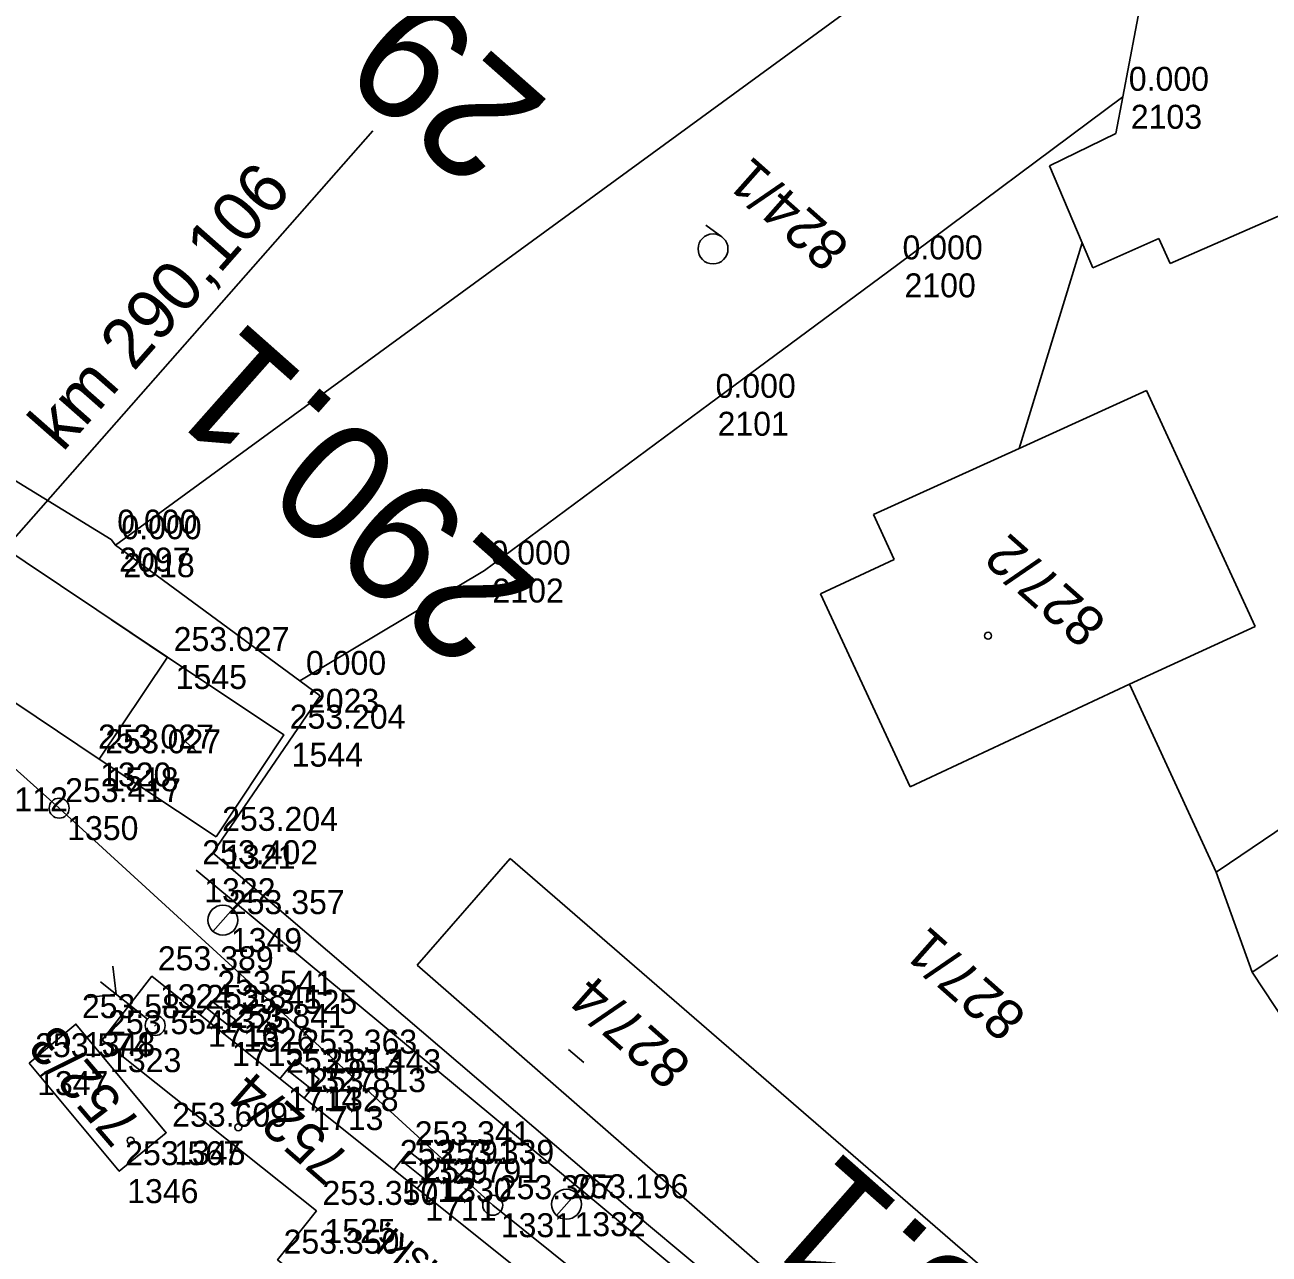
# Model space of a CAD drawing. Extents: x -496688 to -495455, y -1089309 to -1088026.
# Drawn here: x -496316.3 to -496254, y -1088279.1 to -1088217.5 of the extents above; entities that cross this region are included whole.
import ezdxf

# ---------------------------------------------------------------- set-up
doc = ezdxf.new("R2010")
doc.units = 0
for name, color, linetype in [('Vrstva 10', 7, 'Continuous'), ('Vrstva 17', 7, 'Continuous'), ('Vrstva 20', 7, 'Continuous'), ('Vrstva 23', 7, 'Continuous'), ('Vrstva 29', 7, 'Continuous'), ('Vrstva 36', 7, 'Continuous'), ('Vrstva 47', 7, 'Continuous'), ('Vrstva 50', 7, 'Continuous'), ('Vrstva 53', 7, 'Continuous'), ('Vrstva 55', 7, 'Continuous'), ('Vrstva 57', 7, 'Continuous'), ('Vrstva 58', 7, 'Continuous'), ('Vrstva 59', 7, 'Continuous'), ('Vrstva 60', 7, 'Continuous'), ('Vrstva 61', 7, 'Continuous'), ('Vrstva 7', 7, 'Continuous')]:
    doc.layers.add(name, color=color, linetype=linetype)

msp = doc.modelspace()

# ---------------------------------------------------------------- linework, layer by layer
at = {"layer": 'Vrstva 10'}
msp.add_line((-496340.44, -1088269.992), (-496298.917, -1088222.84), dxfattribs=at)
at = {"layer": 'Vrstva 17'}
msp.add_lwpolyline([(-496307.762, -1088259.861), (-496269.8, -1088291.38), (-496248.423, -1088308.125)], dxfattribs=at)
at = {"layer": 'Vrstva 20'}
msp.add_lwpolyline([(-496316.13, -1088269.522), (-496313.788, -1088267.568), (-496309.268, -1088273.004), (-496311.621, -1088274.929), (-496316.13, -1088269.522)], dxfattribs=at)
at = {"layer": 'Vrstva 23'}
for p, q in [((-496259.78, -1088212.78), (-496261.37, -1088221.14)), ((-496261.37, -1088221.14), (-496261.72, -1088222.97)), ((-496261.72, -1088222.97), (-496265.04, -1088224.59)), ((-496265.04, -1088224.59), (-496263.4, -1088228.45)), ((-496259, -1088229.48), (-496251.75, -1088226.32)), ((-496263.4, -1088228.45), (-496262.87, -1088229.7)), ((-496262.87, -1088229.7), (-496259.56, -1088228.24)), ((-496259.56, -1088228.24), (-496259, -1088229.48)), ((-496260.18, -1088235.84), (-496266.56, -1088238.74)), ((-496254.74, -1088247.66), (-496260.18, -1088235.84)), ((-496266.56, -1088238.74), (-496273.85, -1088242.06)), ((-496273.85, -1088242.06), (-496272.81, -1088244.31)), ((-496272.81, -1088244.31), (-496276.5, -1088246.03)), ((-496276.5, -1088246.03), (-496272.01, -1088255.68)), ((-496261.03, -1088250.54), (-496254.74, -1088247.66)), ((-496272.01, -1088255.68), (-496261.03, -1088250.54)), ((-496249.52, -1088261.41), (-496254.9, -1088264.97)), ((-496254.9, -1088264.97), (-496248.71, -1088274.32)), ((-496307.572, -1088267.101), (-496307.006, -1088266.394)), ((-496307.006, -1088266.394), (-496305.804, -1088267.347)), ((-496306.08, -1088267.692), (-496307.278, -1088266.733)), ((-496305.804, -1088267.347), (-496306.374, -1088268.059)), ((-496303.569, -1088270.304), (-496302.8, -1088269.342)), ((-496302.8, -1088269.342), (-496301.602, -1088270.326)), ((-496303.205, -1088269.848), (-496301.994, -1088270.816)), ((-496301.602, -1088270.326), (-496302.359, -1088271.272)), ((-496297.869, -1088274.865), (-496297.123, -1088273.932)), ((-496297.123, -1088273.932), (-496295.941, -1088274.86)), ((-496297.491, -1088274.392), (-496296.318, -1088275.331)), ((-496295.941, -1088274.86), (-496296.696, -1088275.803))]:
    msp.add_line(p, q, dxfattribs=at)
for points in [[(-496306.766, -1088258.19), (-496312.619, -1088254.307), (-496335.736, -1088238.781), (-496332.365, -1088233.683), (-496309.194, -1088249.189), (-496303.385, -1088253.076), (-496306.766, -1088258.19)], [(-496312.619, -1088254.307), (-496309.194, -1088249.189)], [(-496312.479, -1088268.372), (-496309.984, -1088265.171), (-496290.696, -1088280.604), (-496295.221, -1088286.171), (-496303.69, -1088279.36), (-496301.745, -1088276.917), (-496312.479, -1088268.372)]]:
    msp.add_lwpolyline(points, dxfattribs=at)
at = {"layer": 'Vrstva 29'}
msp.add_lwpolyline([(-496228.726, -1088272.089), (-496242.207, -1088304.985), (-496270.468, -1088294.64), (-496292.916, -1088276.634), (-496314.625, -1088256.754), (-496338.738, -1088235.152), (-496372.173, -1088205.903), (-496403.1, -1088180.315), (-496426.737, -1088162.268), (-496430.704, -1088173.66)], dxfattribs=at)
at = {"layer": 'Vrstva 36'}
for centre in [(-496314.625, -1088256.754), (-496292.916, -1088276.634)]:
    msp.add_circle(centre, 0.5, dxfattribs=at)
at = {"layer": 'Vrstva 47'}
for p, q in [((-496306.928, -1088262.922), (-496305.271, -1088261.05)), ((-496289.722, -1088277.146), (-496288.065, -1088275.274))]:
    msp.add_line(p, q, dxfattribs=at)
for centre in [(-496306.431, -1088262.36), (-496289.225, -1088276.584)]:
    msp.add_circle(centre, 0.75, dxfattribs=at)
at = {"layer": 'Vrstva 50'}
for p, q in [((-496311.77, -1088266.074), (-496311.931, -1088264.657)), ((-496310.208, -1088267.324), (-496312.549, -1088265.449)), ((-496311.77, -1088266.074), (-496313.175, -1088266.229)), ((-496309.849, -1088267.676), (-496309.787, -1088267.598))]:
    msp.add_line(p, q, dxfattribs=at)
msp.add_circle((-496309.818, -1088267.637), 0.5, dxfattribs=at)
at = {"layer": 'Vrstva 53'}
for points in [[(-496539.03, -1088065.6), (-496535.97, -1088067.83), (-496531.62, -1088071.46), (-496507.63, -1088096.03), (-496458.59, -1088146.6), (-496452.94, -1088142.96), (-496452.25, -1088138.8), (-496443.22, -1088147.27), (-496395.64, -1088185.72), (-496395.1, -1088185.29), (-496369.57, -1088204.88), (-496360, -1088212.22), (-496349.3, -1088220.43), (-496330.37, -1088232.05), (-496312.02, -1088243.31), (-496311.81, -1088243.59), (-496302.57, -1088250.38)], [(-496302.57, -1088250.38), (-496293.33, -1088244.86), (-496282.06, -1088236.51), (-496272.7, -1088229.58), (-496261.37, -1088221.14), (-496259.78, -1088212.78), (-496258.79, -1088209.96), (-496249.04, -1088205.74), (-496247.06, -1088204.88), (-496237.12, -1088227.8), (-496230.93, -1088242.07), (-496224.34, -1088239.32), (-496222.24, -1088238.44), (-496221.74, -1088238.24), (-496217.87, -1088236.62), (-496206.35, -1088231.82), (-496205.03, -1088234.9), (-496199.66, -1088247.57), (-496188.02, -1088275.91)]]:
    msp.add_lwpolyline(points, dxfattribs=at)
at = {"layer": 'Vrstva 55'}
for p, q in [((-496254.42, -1088201.7), (-496311.81, -1088243.59)), ((-496263.4, -1088228.45), (-496266.56, -1088238.74)), ((-496311.81, -1088243.59), (-496312.02, -1088243.31)), ((-496312.01, -1088247.33), (-496309.2, -1088249.21)), ((-496241.58, -1088249.7), (-496256.02, -1088259.51)), ((-496302.57, -1088250.38), (-496301.558, -1088251.123)), ((-496301.558, -1088251.123), (-496306.928, -1088258.99)), ((-496261.03, -1088250.54), (-496256.69, -1088259.96)), ((-496306.928, -1088258.99), (-496285.12, -1088277.63)), ((-496296.7, -1088264.61), (-496292.05, -1088259.28)), ((-496292.05, -1088259.28), (-496264.72, -1088282.93)), ((-496256.02, -1088259.51), (-496256.69, -1088259.96)), ((-496256.69, -1088259.96), (-496254.9, -1088264.97)), ((-496269.47, -1088288.37), (-496296.7, -1088264.61)), ((-496285.12, -1088277.63), (-496271.2, -1088289.24))]:
    msp.add_line(p, q, dxfattribs=at)
at = {"layer": 'Vrstva 58'}
msp.add_line((-496281.445, -1088228.152), (-496282.251, -1088227.561), dxfattribs=at)
msp.add_circle((-496281.888, -1088228.757), 0.75, dxfattribs=at)
at = {"layer": 'Vrstva 59'}
for p, q in [((-496307.662, -1088253.987), (-496308.41, -1088253.323)), ((-496288.364, -1088269.495), (-496289.118, -1088268.837))]:
    msp.add_line(p, q, dxfattribs=at)
for centre in [(-496268.118, -1088248.123), (-496305.659, -1088272.733), (-496311.048, -1088273.4)]:
    msp.add_circle(centre, 0.175, dxfattribs=at)
at = {"layer": 'Vrstva 60'}
for p, q in [((-496261.37, -1088221.14), (-496261.37, -1088221.14)), ((-496261.37, -1088221.14), (-496261.37, -1088221.14)), ((-496272.7, -1088229.58), (-496272.7, -1088229.58)), ((-496272.7, -1088229.58), (-496272.7, -1088229.58)), ((-496282.06, -1088236.51), (-496282.06, -1088236.51)), ((-496282.06, -1088236.51), (-496282.06, -1088236.51)), ((-496312.02, -1088243.31), (-496312.02, -1088243.31)), ((-496312.02, -1088243.31), (-496312.02, -1088243.31)), ((-496311.81, -1088243.59), (-496311.81, -1088243.59)), ((-496311.81, -1088243.59), (-496311.81, -1088243.59)), ((-496293.33, -1088244.86), (-496293.33, -1088244.86)), ((-496293.33, -1088244.86), (-496293.33, -1088244.86)), ((-496309.194, -1088249.189), (-496309.194, -1088249.189)), ((-496309.194, -1088249.189), (-496309.194, -1088249.189)), ((-496302.57, -1088250.38), (-496302.57, -1088250.38)), ((-496302.57, -1088250.38), (-496302.57, -1088250.38)), ((-496303.385, -1088253.076), (-496303.385, -1088253.076)), ((-496303.385, -1088253.076), (-496303.385, -1088253.076)), ((-496312.977, -1088254.069), (-496312.977, -1088254.069)), ((-496312.977, -1088254.069), (-496312.977, -1088254.069)), ((-496312.619, -1088254.307), (-496312.619, -1088254.307)), ((-496312.619, -1088254.307), (-496312.619, -1088254.307)), ((-496314.625, -1088256.754), (-496314.625, -1088256.754)), ((-496314.625, -1088256.754), (-496314.625, -1088256.754)), ((-496306.766, -1088258.19), (-496306.766, -1088258.19)), ((-496306.766, -1088258.19), (-496306.766, -1088258.19)), ((-496307.762, -1088259.861), (-496307.762, -1088259.861)), ((-496307.762, -1088259.861), (-496307.762, -1088259.861)), ((-496306.431, -1088262.36), (-496306.431, -1088262.36)), ((-496306.431, -1088262.36), (-496306.431, -1088262.36)), ((-496309.984, -1088265.171), (-496309.984, -1088265.171)), ((-496309.984, -1088265.171), (-496309.984, -1088265.171)), ((-496307.006, -1088266.394), (-496307.006, -1088266.394)), ((-496307.006, -1088266.394), (-496307.006, -1088266.394)), ((-496307.572, -1088267.101), (-496307.572, -1088267.101)), ((-496307.572, -1088267.101), (-496307.572, -1088267.101)), ((-496313.788, -1088267.568), (-496313.788, -1088267.568)), ((-496313.788, -1088267.568), (-496313.788, -1088267.568)), ((-496305.804, -1088267.347), (-496305.804, -1088267.347)), ((-496305.804, -1088267.347), (-496305.804, -1088267.347)), ((-496312.479, -1088268.372), (-496312.479, -1088268.372)), ((-496312.479, -1088268.372), (-496312.479, -1088268.372)), ((-496306.374, -1088268.059), (-496306.374, -1088268.059)), ((-496306.374, -1088268.059), (-496306.374, -1088268.059)), ((-496316.13, -1088269.522), (-496316.13, -1088269.522)), ((-496316.13, -1088269.522), (-496316.13, -1088269.522)), ((-496302.8, -1088269.342), (-496302.8, -1088269.342)), ((-496302.8, -1088269.342), (-496302.8, -1088269.342)), ((-496303.569, -1088270.304), (-496303.569, -1088270.304)), ((-496303.569, -1088270.304), (-496303.569, -1088270.304)), ((-496301.602, -1088270.326), (-496301.602, -1088270.326)), ((-496301.602, -1088270.326), (-496301.602, -1088270.326)), ((-496302.359, -1088271.272), (-496302.359, -1088271.272)), ((-496302.359, -1088271.272), (-496302.359, -1088271.272)), ((-496309.268, -1088273.004), (-496309.268, -1088273.004)), ((-496309.268, -1088273.004), (-496309.268, -1088273.004)), ((-496297.123, -1088273.932), (-496297.123, -1088273.932)), ((-496297.123, -1088273.932), (-496297.123, -1088273.932)), ((-496311.621, -1088274.929), (-496311.621, -1088274.929)), ((-496311.621, -1088274.929), (-496311.621, -1088274.929)), ((-496297.869, -1088274.865), (-496297.869, -1088274.865)), ((-496297.869, -1088274.865), (-496297.869, -1088274.865)), ((-496295.941, -1088274.86), (-496295.941, -1088274.86)), ((-496295.941, -1088274.86), (-496295.941, -1088274.86)), ((-496296.696, -1088275.803), (-496296.696, -1088275.803)), ((-496296.696, -1088275.803), (-496296.696, -1088275.803)), ((-496292.916, -1088276.634), (-496292.916, -1088276.634)), ((-496292.916, -1088276.634), (-496292.916, -1088276.634)), ((-496289.225, -1088276.584), (-496289.225, -1088276.584)), ((-496289.225, -1088276.584), (-496289.225, -1088276.584)), ((-496301.745, -1088276.917), (-496301.745, -1088276.917)), ((-496301.745, -1088276.917), (-496301.745, -1088276.917))]:
    msp.add_line(p, q, dxfattribs=at)

# ---------------------------------------------------------------- texts
at = {"layer": 'Vrstva 10'}
msp.add_text('km 290,106', height=2.5, rotation=48.63225, dxfattribs=at).set_placement((-496314.458, -1088238.975))
at = {"layer": 'Vrstva 23'}
msp.add_text('Uh.skl.', height=1.5, rotation=141.19281, dxfattribs=at).set_placement((-496293.535, -1088281.172))
at = {"layer": 'Vrstva 57'}
for s, rotation, p in [('824/1', 138.47617, (-496274.947, -1088228.521)), ('827/2', 138.47617, (-496262.089, -1088247.351)), ('827/1', 138.47617, (-496266.095, -1088267.067)), ('827/4', 138.47617, (-496282.871, -1088269.463)), ('752/3', 130.50406, (-496310.417, -1088272.555)), ('752/4', 138.89312, (-496299.956, -1088274.216))]:
    msp.add_text(s, height=2, rotation=rotation, dxfattribs=at).set_placement(p)
at = {"layer": 'Vrstva 60'}
for s, p in [('2103', (-496260.97, -1088222.74)), ('2103', (-496260.97, -1088222.74)), ('2100', (-496272.3, -1088231.18)), ('2100', (-496272.3, -1088231.18)), ('2101', (-496281.66, -1088238.11)), ('2101', (-496281.66, -1088238.11)), ('2097', (-496311.62, -1088244.91)), ('2097', (-496311.62, -1088244.91)), ('2018', (-496311.41, -1088245.19)), ('2018', (-496311.41, -1088245.19)), ('2102', (-496292.93, -1088246.46)), ('2102', (-496292.93, -1088246.46)), ('1545', (-496308.794, -1088250.789)), ('1545', (-496308.794, -1088250.789)), ('2023', (-496302.17, -1088251.98)), ('2023', (-496302.17, -1088251.98)), ('1544', (-496302.985, -1088254.676)), ('1544', (-496302.985, -1088254.676)), ('1320', (-496312.577, -1088255.669)), ('1320', (-496312.577, -1088255.669)), ('1518', (-496312.219, -1088255.907)), ('1518', (-496312.219, -1088255.907)), ('1350', (-496314.225, -1088258.354)), ('1350', (-496314.225, -1088258.354)), ('1321', (-496306.366, -1088259.79)), ('1321', (-496306.366, -1088259.79)), ('1322', (-496307.362, -1088261.461)), ('1322', (-496307.362, -1088261.461)), ('1349', (-496306.031, -1088263.96)), ('1349', (-496306.031, -1088263.96)), ('1324', (-496309.584, -1088266.771)), ('1324', (-496309.584, -1088266.771)), ('1325', (-496306.606, -1088267.994)), ('1325', (-496306.606, -1088267.994)), ('1348', (-496313.388, -1088269.168)), ('1348', (-496313.388, -1088269.168)), ('1716', (-496307.172, -1088268.701)), ('1716', (-496307.172, -1088268.701)), ('1326', (-496305.404, -1088268.947)), ('1326', (-496305.404, -1088268.947)), ('1715', (-496305.974, -1088269.659)), ('1715', (-496305.974, -1088269.659)), ('1323', (-496312.079, -1088269.972)), ('1323', (-496312.079, -1088269.972)), ('1327', (-496302.4, -1088270.942)), ('1327', (-496302.4, -1088270.942)), ('1347', (-496315.73, -1088271.122)), ('1347', (-496315.73, -1088271.122)), ('1714', (-496303.169, -1088271.904)), ('1714', (-496303.169, -1088271.904)), ('1328', (-496301.202, -1088271.926)), ('1328', (-496301.202, -1088271.926)), ('1713', (-496301.959, -1088272.872)), ('1713', (-496301.959, -1088272.872)), ('1345', (-496308.868, -1088274.604)), ('1345', (-496308.868, -1088274.604)), ('1329', (-496296.723, -1088275.532)), ('1329', (-496296.723, -1088275.532)), ('1346', (-496311.221, -1088276.529)), ('1346', (-496311.221, -1088276.529)), ('1712', (-496297.469, -1088276.465)), ('1712', (-496297.469, -1088276.465)), ('1330', (-496295.541, -1088276.46)), ('1330', (-496295.541, -1088276.46)), ('1711', (-496296.296, -1088277.403)), ('1711', (-496296.296, -1088277.403)), ('1331', (-496292.516, -1088278.234)), ('1331', (-496292.516, -1088278.234)), ('1332', (-496288.825, -1088278.184)), ('1332', (-496288.825, -1088278.184)), ('1525', (-496301.345, -1088278.517)), ('1525', (-496301.345, -1088278.517))]:
    msp.add_text(s, height=1.2, dxfattribs=at).set_placement(p)
at = {"layer": 'Vrstva 61'}
for s, p in [('0.000', (-496261.07, -1088220.84)), ('0.000', (-496261.07, -1088220.84)), ('0.000', (-496272.4, -1088229.28)), ('0.000', (-496272.4, -1088229.28)), ('0.000', (-496281.76, -1088236.21)), ('0.000', (-496281.76, -1088236.21)), ('0.000', (-496311.72, -1088243.01)), ('0.000', (-496311.72, -1088243.01)), ('0.000', (-496311.51, -1088243.29)), ('0.000', (-496311.51, -1088243.29)), ('0.000', (-496293.03, -1088244.56)), ('0.000', (-496293.03, -1088244.56)), ('253.027', (-496308.894, -1088248.889)), ('253.027', (-496308.894, -1088248.889)), ('0.000', (-496302.27, -1088250.08)), ('0.000', (-496302.27, -1088250.08)), ('253.204', (-496303.085, -1088252.776)), ('253.204', (-496303.085, -1088252.776)), ('253.027', (-496312.677, -1088253.769)), ('253.027', (-496312.677, -1088253.769)), ('253.027', (-496312.319, -1088254.007)), ('253.027', (-496312.319, -1088254.007)), ('253.417', (-496314.325, -1088256.454)), ('253.417', (-496314.325, -1088256.454)), ('253.112', (-496319.991, -1088256.916)), ('253.112', (-496319.991, -1088256.916)), ('253.204', (-496306.466, -1088257.89)), ('253.204', (-496306.466, -1088257.89)), ('253.402', (-496307.462, -1088259.561)), ('253.402', (-496307.462, -1088259.561)), ('253.357', (-496306.131, -1088262.06)), ('253.357', (-496306.131, -1088262.06)), ('253.389', (-496309.684, -1088264.871)), ('253.389', (-496309.684, -1088264.871)), ('253.541', (-496306.706, -1088266.094)), ('253.541', (-496306.706, -1088266.094)), ('253.582', (-496313.488, -1088267.268)), ('253.582', (-496313.488, -1088267.268)), ('253.841', (-496307.272, -1088266.801)), ('253.841', (-496307.272, -1088266.801)), ('253.525', (-496305.504, -1088267.047)), ('253.525', (-496305.504, -1088267.047)), ('253.841', (-496306.074, -1088267.759)), ('253.841', (-496306.074, -1088267.759)), ('253.554', (-496312.179, -1088268.072)), ('253.554', (-496312.179, -1088268.072)), ('253.363', (-496302.5, -1088269.042)), ('253.363', (-496302.5, -1088269.042)), ('253.574', (-496315.83, -1088269.222)), ('253.574', (-496315.83, -1088269.222)), ('253.813', (-496303.269, -1088270.004)), ('253.813', (-496303.269, -1088270.004)), ('253.443', (-496301.302, -1088270.026)), ('253.443', (-496301.302, -1088270.026)), ('253.813', (-496302.059, -1088270.972)), ('253.813', (-496302.059, -1088270.972)), ('253.609', (-496308.968, -1088272.704)), ('253.609', (-496308.968, -1088272.704)), ('253.341', (-496296.823, -1088273.632)), ('253.341', (-496296.823, -1088273.632)), ('253.567', (-496311.321, -1088274.629)), ('253.567', (-496311.321, -1088274.629)), ('253.791', (-496297.569, -1088274.565)), ('253.791', (-496297.569, -1088274.565)), ('253.339', (-496295.641, -1088274.56)), ('253.339', (-496295.641, -1088274.56)), ('253.791', (-496296.396, -1088275.503)), ('253.791', (-496296.396, -1088275.503)), ('253.350', (-496301.445, -1088276.617)), ('253.350', (-496301.445, -1088276.617)), ('253.307', (-496292.616, -1088276.334)), ('253.307', (-496292.616, -1088276.334)), ('253.196', (-496288.925, -1088276.284)), ('253.196', (-496288.925, -1088276.284)), ('253.350', (-496303.39, -1088279.06)), ('253.350', (-496303.39, -1088279.06))]:
    msp.add_text(s, height=1.2, dxfattribs=at).set_placement(p)
at = {"layer": 'Vrstva 7'}
for s, rotation, p in [('29.4', 138.55699, (-496289.96, -1088221.511)), ('290.1', 138.478, (-496290.448, -1088245.61)), ('116.1', 138.55701, (-496260.617, -1088287.12))]:
    msp.add_text(s, height=6, rotation=rotation, dxfattribs=at).set_placement(p)

doc.saveas('drawing.dxf')
